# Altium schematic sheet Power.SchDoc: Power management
size A4; Author: Ph.A; SheetNumber: 6; SheetTotal: 8
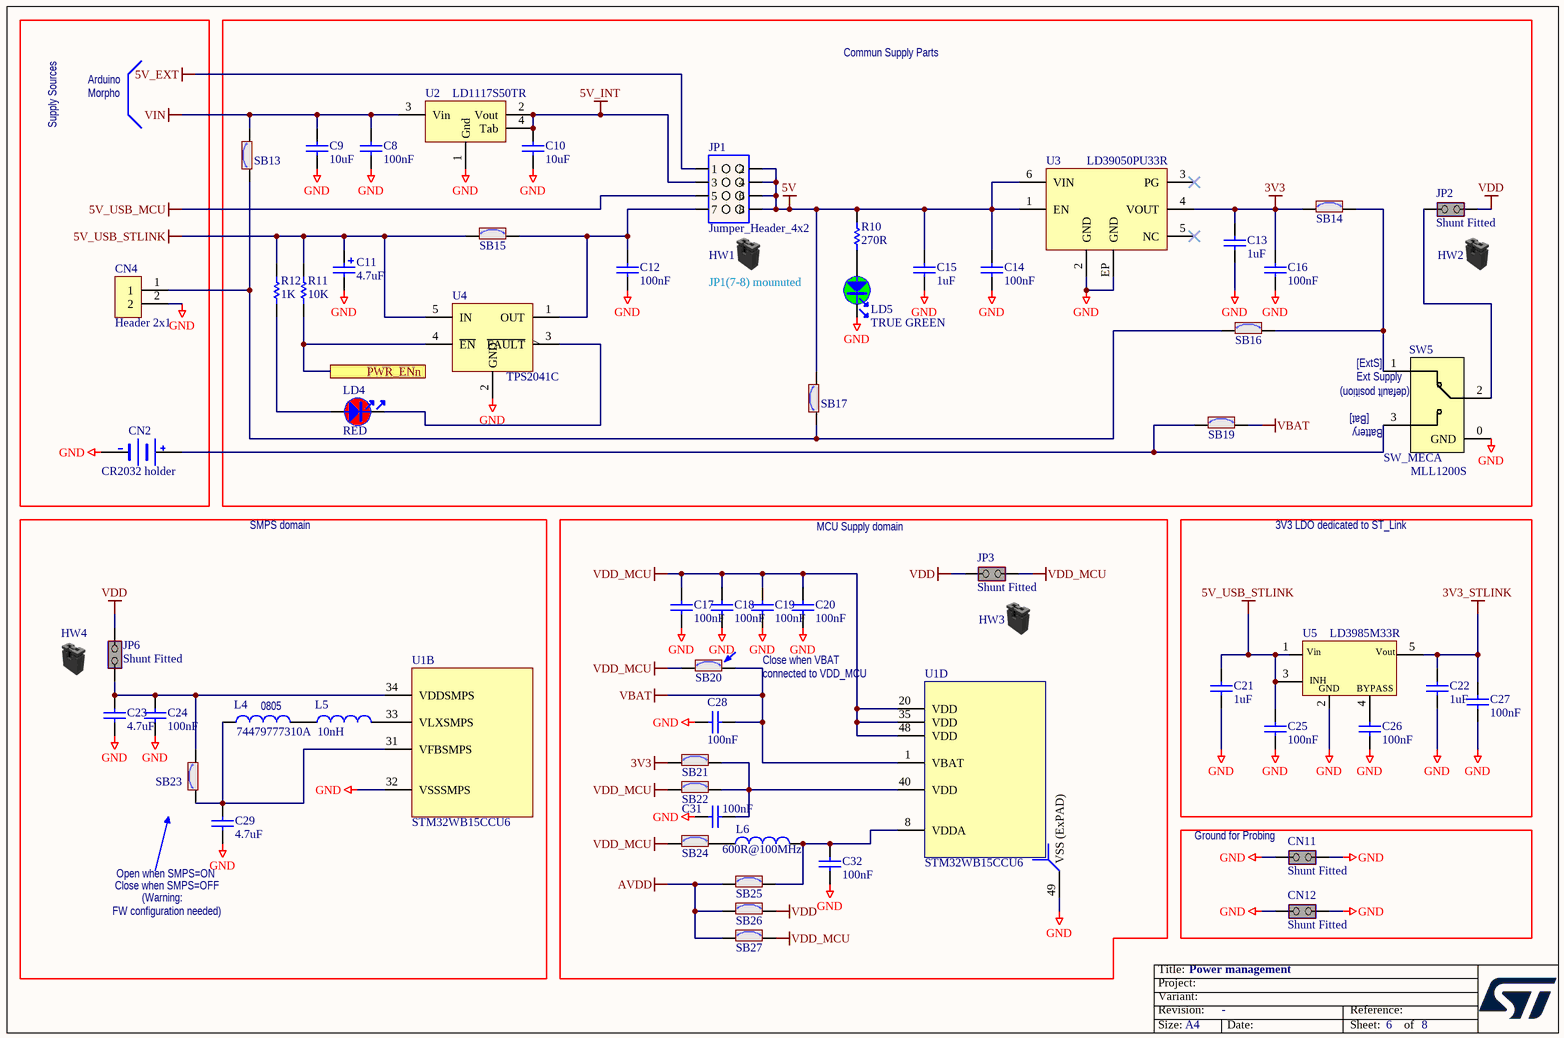
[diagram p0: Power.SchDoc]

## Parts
C8  value 100nF  [C0603]  (hidden comment: Capacitor)
C9  value 10uF  [C0805]  (hidden comment: Capacitor)
C10  value 10uF  [C0805]  (hidden comment: Capacitor)
C11  value 4.7uF  [CPOL_TAJ-A_1206_H180]  (hidden comment: Cap_POL_TANA)
C12  value 100nF  [C0402]  (hidden comment: Capacitor)
C13  value 1uF  [C0603]  (hidden comment: Capacitor)
C14  value 100nF  [C0402]  (hidden comment: Capacitor)
C15  value 1uF  [C0603]  (hidden comment: Capacitor)
C16  value 100nF  [C0402]  (hidden comment: Capacitor)
C17  value 100nF  [C0402]  (hidden comment: Capacitor)
C18  value 100nF  [C0402]  (hidden comment: Capacitor)
C19  value 100nF  [C0402]  (hidden comment: Capacitor)
C20  value 100nF  [C0402]  (hidden comment: Capacitor)
C21  value 1uF  [C0603]  (hidden comment: Capacitor)
C22  value 1uF  [C0603]  (hidden comment: Capacitor)
C23  value 4.7uF  [C0402]  (hidden comment: Capacitor)
C24  value 100nF  [C0402]  (hidden comment: Capacitor)
C25  value 100nF  [C0402]  (hidden comment: Capacitor)
C26  value 100nF  [C0402]  (hidden comment: Capacitor)
C27  value 100nF  [C0402]  (hidden comment: Capacitor)
C28  value 100nF  [C0402]  (hidden comment: Capacitor)
C29  value 4.7uF  [C0402]  (hidden comment: Capacitor)
C31  value 100nF  [C0402]  (hidden comment: Capacitor)
C32  value 100nF  [C0402]  (hidden comment: Capacitor)
CN2  value CR2032 holder  [BAT_RENATA-SMTU2032-LF_KEYSTONE-1769533_CR2032_SMD_2P_DI]  (hidden comment: BATTERY HOLDER)
CN4  Header 2x1  [CON_SAMTEC_TSW-102-07-G-S]
CN11  value Shunt Fitted  [CON_SAMTEC_TSW-102-07-G-S]  (hidden comment: Jumper_Header 2x1 Fitted)
CN12  value Shunt Fitted  [CON_SAMTEC_TSW-102-07-G-S]  (hidden comment: Jumper_Header 2x1 Fitted)
HW1  Shunt Black 2.54mm  (value not drawn)  (mechanical)
HW2  Shunt Black 2.54mm  (value not drawn)  (mechanical)
HW3  Shunt Black 2.54mm  (value not drawn)  (mechanical)
HW4  Shunt Black 2.54mm  (value not drawn)  (mechanical)
JP1  value Jumper_Header_4x2  [CON_SAMTEC_TSW-104-07-X-D]  (hidden comment: Jumper_Header 4x2)
JP2  value Shunt Fitted  [CON_SAMTEC_TSW-102-07-G-S]  (hidden comment: Jumper_Header 2x1 Fitted)
JP3  value Shunt Fitted  [CON_SAMTEC_TSW-102-07-G-S]  (hidden comment: Jumper_Header 2x1 Fitted)
JP6  value Shunt Fitted  [CON_SAMTEC_TSW-102-07-G-S]  (hidden comment: Jumper_Header 2x1 Fitted)
L4  value 74479777310A  [IND_0805_WURTH_74479777310A]  (hidden comment: Inductor)
L5  value 10nH  [IND_0402_MURATA_LQW15AN_H0P5]  (hidden comment: Inductor)
L6  value 600R@100MHz  [L0603]  (hidden comment: BEAD)
LD4  value RED  [LED_0603_VISHAY_VLMS1300-GS08_RED_1A2K_H0P8]  (hidden comment: LED_red)
LD5  value TRUE GREEN  [LED_0603_VISHAY_VLMTG1300-GS08_GREEN_1A2K_H0P8]  (hidden comment: LED_green)
R10  value 270R  [R0402]  (hidden comment: Resistor)
R11  value 10K  [R0402]  (hidden comment: Resistor)
R12  value 1K  [R0402]  (hidden comment: Resistor)
SB13  SB_ON  [SOLDER-BRIDGE_R0402-0R]  (value not drawn)
SB14  SB_ON  [SOLDER-BRIDGE_R0402-0R]  (value not drawn)
SB15  SB_ON  [SOLDER-BRIDGE_R0402-0R]  (value not drawn)
SB16  SB_ON  [SOLDER-BRIDGE_R0402-0R]  (value not drawn)
SB17  SB_ON  [SOLDER-BRIDGE_R0402-0R]  (value not drawn)
SB19  SB_ON  [SOLDER-BRIDGE_R0402-0R]  (value not drawn)
SB20  SB_ON  [SOLDER-BRIDGE_R0402-0R]  (value not drawn)
SB21  SB_ON  [SOLDER-BRIDGE_R0402-0R]  (value not drawn)
SB22  SB_ON  [SOLDER-BRIDGE_R0402-0R]  (value not drawn)
SB23  SB_ON  [SOLDER-BRIDGE_R0402-0R]  (value not drawn)
SB24  SB_ON  [SOLDER-BRIDGE_R0402-0R]  (value not drawn)
SB25  SB_ON  [SOLDER-BRIDGE_R0402-0R]  (value not drawn)
SB26  SB_ON  [SOLDER-BRIDGE_R0402-0R]  (value not drawn)
SB27  SB_ON  [SOLDER-BRIDGE_R0402-0R]  (value not drawn)
SW5  SW_MECA  value MLL1200S  [SWI_SPDT-RA_TE-CONNECTIVITY_MLL1200S_1P2T]
U1  value STM32WB15CCU6  [ICC_UFQFPN48-EPAD_7X7_H0P55_P050]  (hidden comment: STM32WB15_QFN48)  (parts B,D of 5)
U2  LD1117S50TR  [REG_SOT223-TAB]
U3  LD39050PU33R  [ICC_DFN6-EPAD_3X3_P095]
U4  TPS2041C  [MOS_SOT23-5L]
U5  LD3985M33R  [REG_SOT23-5L]

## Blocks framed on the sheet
3V3 LDO dedicated to ST_Link: C21 C22 C25-C27 U5
Ground for Probing: CN11 CN12

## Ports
PWR_ENn

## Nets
3V3: C13.2 C16.2 SB14.1 SB21.1 U3.4(VOUT)
3V3_STLINK: C22.2 C27.2 U5.5(Vout)
5V: C14.2 C15.2 JP1.2 JP1.4 JP1.6 JP1.8 R10.2 SB17.2 U3.1(EN) U3.6(VIN)
5V_EXT: JP1.1
5V_INT: C10.1 JP1.3 U2.2(Vout) U2.4(Tab)
5V_USB_MCU: JP1.5
5V_USB_STLINK: C11.1 C21.2 C25.2 R11.2 R12.2 SB15.1 U4.5(IN) U5.1(Vin) U5.3(CE)
AVDD: SB25.1 SB26.1 SB27.1
GND: C8.1 C9.2 C10.2 C11.2 C12.1 C13.1 C14.1 C15.1 C16.1 C17.1 C18.1 C19.1 C20.1 C21.1 C22.1 C23.1 C24.1 C25.1 C26.1 C27.1 C28.2 C29.1 C31.1 C32.1 CN2.2(-) CN4.2 CN11.1(COMMON) CN11.2(NO) CN12.1(COMMON) CN12.2(NO) LD5.2 SW5.0(GND) U1.32(VSSSMPS) U1.49(VSS_(ExPAD)) U2.1(Gnd) U3.2(GND) U3.EP(GND) U4.2(GND) U5.2(GND)
VBAT: C28.1 SB19.2 SB20.2 U1.1(VBAT)
VDD: JP2.2(NO) JP3.1(COMMON) JP6.1(COMMON) SB26.2
VDD_MCU: C17.2 C18.2 C19.2 C20.2 JP3.2(NO) SB20.1 SB22.1 SB24.1 SB27.2 U1.20(VDD) U1.35(VDD) U1.48(VDD)
VIN: C8.2 C9.1 SB13.2 U2.3(Vin)
PWR_ENn: R11.1 U4.4(~{EN}) ; port PWR_ENn
NetC12_2: C12.2 JP1.7 SB15.2 U4.1(OUT)
NetC23_2: C23.2 C24.2 JP6.2(NO) SB23.2 U1.34(VDDSMPS)
NetC26_2: C26.2 U5.4(BYPASS)
NetC29_2: C29.2 L4.1 SB23.1 U1.31(VFBSMPS)
NetC31_2: C31.2 SB21.2 SB22.2 U1.40(VDD)
NetC32_2: C32.2 L6.2 SB25.2 U1.8(VDDA)
NetCN2_1: CN2.1(+) SB19.1 SW5.3
NetCN4_1: CN4.1 SB13.1 SB16.1 SB17.1
NetJP2_1: JP2.1(COMMON) SW5.2
NetL4_2: L4.2 L5.1
NetL5_2: L5.2 U1.33(VLXSMPS)
NetL6_1: L6.1 SB24.2
NetLD4_1: LD4.1 R12.1
NetLD4_2: LD4.2 U4.3(~{FAULT})
NetLD5_1: LD5.1 R10.1
NetSB14_2: SB14.2 SB16.2 SW5.1

Not connected (* = marked no-connect by the designer): U3 3(PG)* 5(NC)*

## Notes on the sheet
- Arduino
- Morpho
- Commun Supply Parts
- Supply Sources
- JP1(7-8) mounuted
- (near SW5) Ext Supply
- (near SW5) [ExtS]
- (near SW5) (default position)
- (near SW5) [Bat]
- (near SW5) Battery
- SMPS domain
- MCU Supply domain
- (near L4) 0805
- Close when VBAT
- connected to VDD_MCU
- FW configuration needed)
- (near C29) Close when SMPS=OFF
- (near C29) Open when SMPS=ON
- (Warning:

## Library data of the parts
C8 = MCD-01099: Capacitor, MLCC, 100nF, 50V, X7R, +/-10%, 0603, T=0.8mm; Manufacturer_Part_Number: CC0603KRX7R9BB104; Manufacturer: YAGEO; BMS_Part_Number: 9142278; Part_Preference: Recommended; Order_Code_RS: 669-8767
C9 C10 = MCD-00014: Capacitor, MLCC, 10uF, 25V, X5R, +/-10%, 0805, T=0,85mm; Manufacturer_Part_Number: CC0805KRX5R8BB106; Manufacturer: YAGEO; Part_Preference: Recommended
C11 = MCD-00007: Capacitor, Tantalum, 4.7uF, 16V, 4ohms, +/-10%, pkg Type_A (3216 metric), T=1.6mm; Manufacturer_Part_Number: TAJA475K016R; Manufacturer: AVX; Part_Preference: Recommended; Order_Code_RS: 464-9132
C12 C14 C16-C20 C24-C28 C31 C32 = MCD-00006: Capacitor, MLCC, 100nF, 16V, X7R, +/-10%, 0402, T=0.5mm; Manufacturer_Part_Number: CC0402KRX7R7BB104; Manufacturer: YAGEO; Alternate_Manufacturer_Part_Number: GCM155R71C104KA55D; Alternate_Manufacturer: MURATA; Part_Preference: Recommended; Order_Code_RS: 616-9701
C13 C15 C21 C22 = MCD-00010: Capacitor, MLCC, 1uF, 16V, X5R, +/-10%, 0603, T=0,8mm; Manufacturer_Part_Number: CC0603KRX5R7BB105; Manufacturer: YAGEO; Part_Preference: Recommended
C23 C29 = MCD-01356: Capacitor, MLCC, 4.7uF, 6V3, X5R, +/-20%, 0402, T=0,5mm; Manufacturer_Part_Number: GRM155R60J475ME47; Manufacturer: MURATA; Alternate_Manufacturer_Part_Number: GRM155R60J475ME87; Part_Preference: Recommended; Order_Code_RS: 814-5230
CN2 = MCD-02071: Battery Coin Cell holder, CR2032_20mm, Height 5.4mm; Part_Type: Connector; Manufacturer_Part_Number: SMTU2032-LF; Manufacturer: RENATA; Alternate_Manufacturer_Part_Number: KEYSTONE; Alternate_Manufacturer: 1060TR; Part_Preference: Recommended
CN4 = MCD-00032: Header, 2x1, 2,54mm, VR, TH, Height 5.84mm/2.54mm; Manufacturer_Part_Number: TSW-102-07-G-S; Manufacturer: SAMTEC; Part_Type: Connector; Part_Preference: Recommended; Alternate_Manufacturer: JIUBABA; Alternate_Manufacturer_Part_Number: 313102S111116
CN11 CN12 JP2 JP3 JP6 = MCD-00683: Header, 2x1, 2,54mm, VR, TH, Height 5.84mm/2.54mm - Shunt Fitted by default; Part_Type: Connector; Manufacturer_Part_Number: TSW-102-07-G-S; Manufacturer: SAMTEC; Alternate_Manufacturer_Part_Number: 313102S111116; Alternate_Manufacturer: LIANYI; Part_Preference: Recommended
HW1-HW4 = MCD-00043: SHUNT 2.54mm BLACK; Manufacturer_Part_Number: SNT-100-BK-G; Manufacturer: SAMTEC; Part_Type: Misc; Part_Preference: Recommended; Alternate_Manufacturer: JIUBABA; Alternate_Manufacturer_Part_Number: 316102S111A; Value: SNT-100-BK-G
JP1 = MCD-00633: Header, 4x2, 2,54mm, VR, TH, Height 5.84mm/2.54mm; Part_Type: Connector; Manufacturer_Part_Number: TSW-104-07-G-D; Manufacturer: SAMTEC; Part_Preference: Recommended
L4 = MCD-01676: PMI Series 10 μH ±20% Multilayer SMD Inductor, 0805 25MHz 650mA dc 500mΩ Rdc; Manufacturer: WURTH ELEKTRONIK; Part_Preference: Recommended
L5 = MCD-02063: Inductor, 10nH +-2%, 100mA max,1.3 ohm DC max, Q min = 13,0402; Manufacturer_Part_Number: LQP15MN10NG02; Manufacturer: MURATA; Alternate_Manufacturer_Part_Number: 744901110; Alternate_Manufacturer: WURTH ELECTRONIK; Part_Preference: Forbidden; Order_Code_RS: 167-3827
L6 = MCD-00047: SMD Chip ferrite bead, 600R@100MHz +/-25%, 350mA, 500mohm DC, 0603, T=0.8mm; Part_Type: Inductor; Manufacturer_Part_Number: FCM1608KF-601T03; Manufacturer: TAI-TECH; Part_Preference: Recommended
LD4 = MCD-00587: LED Red, 0603 SMD, 2V Forward Voltage; Part_Type: Display; Manufacturer_Part_Number: VLMS1300-GS08; Manufacturer: VISHAY; Alternate_Manufacturer_Part_Number: LS Q976-NR-1; Alternate_Manufacturer: OSRAM OPTO SEMICONDUCTORS; Part_Preference: Recommended
LD5 = MCD-00589: LED Green, 0603 SMD, Fw Voltage = 2.8V - 3.6V; Part_Type: Display; Manufacturer_Part_Number: VLMTG1300-GS08; Manufacturer: VISHAY; Alternate_Manufacturer_Part_Number: LG Q396-PS-35; Alternate_Manufacturer: OSRAM OPTO SEMICONDUCTORS; Part_Preference: Recommended; Order_Code_RS: 7730452
R10 = MCD-00441: Resistor,270R,0402,1%,1/16W; Manufacturer_Part_Number: RC0402FR-07270RL; Manufacturer: YAGEO; Part_Preference: Recommended
R11 = MCD-00053: Resistor,10K,0402,1%,1/16W; Manufacturer_Part_Number: RC0402FR-0710KL; Manufacturer: YAGEO; BMS_Part_Number: 9131590; Part_Preference: Recommended
R12 = MCD-00061: Resistor,1K,0402,1%,1/16W; Manufacturer_Part_Number: RC0402FR-071KL; Manufacturer: YAGEO; Part_Preference: Recommended
SB13-SB17 SB19-SB27 = MCD-01618: Solder Bridge 0402 ON; Part_Type: Misc; Manufacturer_Part_Number: RC0402JR-070RL; Manufacturer: YAGEO; Part_Preference: Recommended; Order_Code_RS: 618-5804
SW5 = MCD-02081: SPDT RA SMT SLIDE SWITCH; Part_Type: Connector; Manufacturer: TE CONNECTIVITY; Part_Preference: Recommended; Order_Code_RS: 2552311300
U1 = MCD-02058: Multiprotocol wireless 32-bit MCU ARM®-based Cortex®-M4 with FPU, Bluetooth® Low-Energy and 802.15.4 radio solution; Part_Type: IC; Manufacturer: STMICROELECTRONICS; Part_Preference: Recommended; Manufacturer_HQ_COO: EU; Component_Country_Of_Origin: China
U2 = MCD-00088: IC REG LDO 5V 0.8A SOT223; Manufacturer: STMICROELECTRONICS; BMS_Part_Number: 9176133; Part_Preference: Recommended; Manufacturer_HQ_COO: EU
U3 = MCD-00215: Low quiescent current and low noise voltage regulators; Part_Type: IC; Manufacturer: STMICROELECTRONICS; BMS_Part_Number: 9176126; Part_Preference: Recommended; Manufacturer_HQ_COO: EU
U4 = MCD-01785: 5V Power Switch, 0.85A, RDSon 130mOhm max, with active low enable pin; Part_Type: IC; Manufacturer_Part_Number: TPS2041CDBVT; Manufacturer: TEXAS INSTRUMENTS; Part_Preference: Recommended
U5 = MCD-00086: Ultra low drop-low noise BiCMOS voltage, regulators low ESR capacitors compatible; Part_Type: IC; Manufacturer: STMICROELECTRONICS; BMS_Part_Number: 9176161; Part_Preference: Recommended; Manufacturer_HQ_COO: EU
